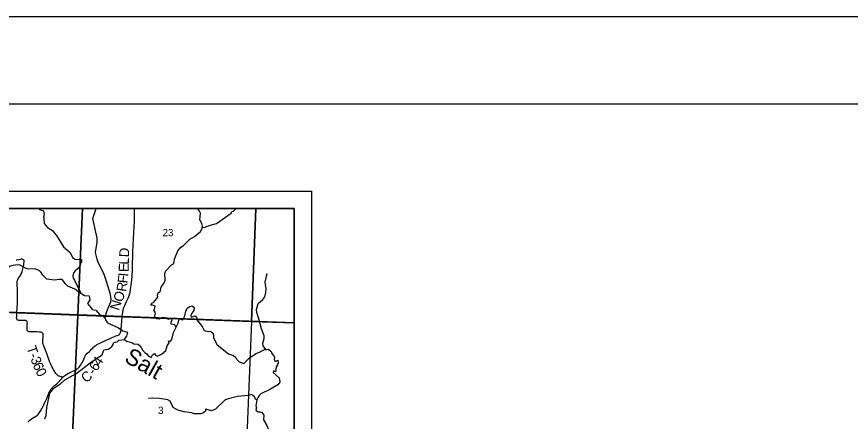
# Model space of a CAD drawing. Extents: x 0 to 34, y 0 to 22.
# Drawn here: x 7.308 to 12.092, y 19.68 to 22 of the extents above; entities that cross this region are included whole.
import ezdxf

# ---------------------------------------------------------------- set-up
doc = ezdxf.new("R2010")
doc.units = 0
for name, color, linetype in [('GM_X_County_Road', 7, 'Continuous'), ('GM_X_County_Road_Text', 7, 'Continuous'), ('GM_X_Minor_River', 7, 'Continuous'), ('GM_X_Minor_River_Text', 7, 'Continuous'), ('GM_X_Rail_Line', 7, 'Continuous'), ('GM_X_Section', 7, 'Continuous'), ('GM_X_Section_Text', 7, 'Continuous'), ('GM_X_Township_Road', 7, 'Continuous'), ('GM_X_Township_Road_Text', 7, 'Continuous'), ('GM_X_Unincorporated_Text', 7, 'Continuous'), ('SH_Border', 7, 'Continuous'), ('SH_Cut_Line', 7, 'Continuous'), ('SH_Data', 7, 'Continuous')]:
    doc.layers.add(name, color=color, linetype=linetype)

msp = doc.modelspace()

# ---------------------------------------------------------------- linework, layer by layer
at = {"layer": 'GM_X_County_Road'}
for points in [[(7.9141, 20.2771), (7.9142, 20.2781), (7.9144, 20.28), (7.9154, 20.2936), (7.9168, 20.306), (7.9185, 20.3152), (7.9208, 20.3243), (7.9236, 20.3332), (7.9281, 20.3449), (7.9317, 20.3535), (7.938, 20.3675), (7.948, 20.3866), (7.952, 20.3955), (7.9564, 20.4078), (7.9596, 20.4197), (7.9621, 20.4337), (7.9662, 20.4765), (7.9701, 20.5077), (7.9715, 20.5235), (7.9722, 20.5378), (7.9726, 20.5533), (7.9733, 20.5875), (7.9741, 20.6247), (7.9748, 20.6496), (7.9798, 20.7647), (7.9837, 20.8261), (7.9851, 20.8606), (7.9844, 20.9)], [(7.5721, 19.9341), (7.5765, 19.9372), (7.5828, 19.9414), (7.5878, 19.9451), (7.6019, 19.9536), (7.6152, 19.9603), (7.6312, 19.9682), (7.6433, 19.9738), (7.6512, 19.9783), (7.6591, 19.9835), (7.666, 19.9899), (7.6708, 19.9955), (7.6761, 20.0031), (7.681, 20.0109), (7.6854, 20.0187), (7.6894, 20.027), (7.6929, 20.0355), (7.6985, 20.05), (7.7004, 20.0544), (7.703, 20.0584), (7.7049, 20.0609), (7.709, 20.0657), (7.7136, 20.0699), (7.7183, 20.074), (7.7253, 20.0801), (7.7297, 20.0844), (7.7381, 20.0935), (7.7443, 20.1004), (7.751, 20.107), (7.7558, 20.1111), (7.7609, 20.1148), (7.7662, 20.1181), (7.7771, 20.1239), (7.7939, 20.1321), (7.8596, 20.163), (7.8697, 20.1672), (7.8776, 20.1694), (7.885, 20.1713), (7.8907, 20.1735), (7.8943, 20.1758), (7.8975, 20.1787), (7.9004, 20.1819), (7.9027, 20.1856), (7.9046, 20.1901), (7.9059, 20.1953), (7.9076, 20.2071), (7.9123, 20.2534), (7.9141, 20.2771)], [(7.3715, 19.6746), (7.3776, 19.6805), (7.3843, 19.6867), (7.3917, 19.6923), (7.3997, 19.6979), (7.4224, 19.7122), (7.428, 19.7162), (7.4323, 19.7196), (7.4361, 19.7241), (7.4399, 19.7298), (7.4429, 19.7356), (7.4521, 19.7521), (7.4633, 19.7738), (7.4686, 19.7848), (7.4817, 19.8114), (7.4877, 19.8267), (7.4932, 19.841), (7.4976, 19.8501), (7.5016, 19.8573), (7.5069, 19.8654), (7.5107, 19.8702), (7.5148, 19.8755), (7.5188, 19.8795), (7.5248, 19.8845), (7.5305, 19.8893), (7.5382, 19.8951), (7.5448, 19.9008), (7.5501, 19.9061), (7.5549, 19.9115), (7.5614, 19.9193), (7.5666, 19.9263), (7.5698, 19.931), (7.5721, 19.9341)]]:
    msp.add_lwpolyline(points, dxfattribs=at)
at = {"layer": 'GM_X_Minor_River'}
for points in [[(7.4372, 20.9), (7.4388, 20.8942), (7.4619, 20.8875), (7.4651, 20.8667), (7.4614, 20.853), (7.4648, 20.8428), (7.4654, 20.8137), (7.4859, 20.7911), (7.5133, 20.7742), (7.5228, 20.7603), (7.5361, 20.7452), (7.5774, 20.6803), (7.6147, 20.6473), (7.6277, 20.6193), (7.6414, 20.6107), (7.6512, 20.6085)], [(7.8111, 20.2745), (7.8163, 20.2791), (7.8275, 20.3149), (7.8488, 20.3643), (7.8499, 20.3791), (7.8456, 20.4075), (7.8228, 20.4821), (7.8077, 20.5283), (7.7775, 20.5865), (7.7694, 20.6096), (7.7612, 20.6483), (7.7707, 20.7075), (7.7691, 20.7299), (7.7446, 20.8435), (7.7645, 20.9)], [(8.2227, 20.2186), (8.2148, 20.2333), (8.1944, 20.2366), (8.1947, 20.2479), (8.2003, 20.2616), (8.1908, 20.2695), (8.1791, 20.2642), (8.1582, 20.2739), (8.1456, 20.2757), (8.1252, 20.2665), (8.112, 20.2672), (8.1025, 20.2732), (8.0997, 20.2846), (8.1057, 20.296), (8.1038, 20.3058), (8.0961, 20.3175), (8.1018, 20.3282), (8.1028, 20.34), (8.088, 20.3459), (8.0774, 20.3463), (8.0834, 20.3573), (8.0936, 20.3619), (8.1132, 20.3836), (8.1181, 20.3931), (8.1154, 20.4034), (8.1199, 20.4159), (8.1308, 20.422), (8.1367, 20.4486), (8.1548, 20.4741), (8.1607, 20.489), (8.1579, 20.5276), (8.165, 20.5425), (8.197, 20.5776), (8.2087, 20.5837), (8.2121, 20.5951), (8.2146, 20.6107), (8.2337, 20.6574), (8.2506, 20.6795), (8.2646, 20.6879), (8.3027, 20.7253), (8.3291, 20.7403), (8.3495, 20.7571), (8.3623, 20.7693), (8.3728, 20.7849), (8.3754, 20.7997), (8.3715, 20.8149), (8.3596, 20.836), (8.3621, 20.8728), (8.3567, 20.8849), (8.3456, 20.9)], [(8.3738, 20.7904), (8.3906, 20.7926), (8.4136, 20.8026), (8.4556, 20.8142), (8.5383, 20.8731), (8.5432, 20.883), (8.553, 20.8857), (8.5671, 20.9)], [(7.6538, 20.4297), (7.6424, 20.4387), (7.6026, 20.4559), (7.5878, 20.4679), (7.5687, 20.4928), (7.5543, 20.4938), (7.526, 20.4894), (7.4806, 20.4959), (7.4585, 20.5178), (7.4486, 20.5328), (7.4364, 20.5445), (7.4125, 20.5534), (7.3777, 20.5528), (7.3622, 20.5554), (7.3246, 20.5782), (7.3, 20.5754), (7.2879, 20.5734), (7.2649, 20.5668), (7.2371, 20.5325), (7.2282, 20.5173), (7.2095, 20.4672), (7.2124, 20.4392), (7.2181, 20.4286)], [(7.6512, 20.6085), (7.6804, 20.6091), (7.6793, 20.5966), (7.6655, 20.5597), (7.6429, 20.5421)], [(7.6429, 20.5421), (7.635, 20.5315), (7.6299, 20.5133), (7.6318, 20.5008), (7.6395, 20.4902)], [(8.7314, 20.0914), (8.7386, 20.0914), (8.7229, 20.1133), (8.7213, 20.1284), (8.7283, 20.1554), (8.7279, 20.171), (8.7121, 20.2107), (8.702, 20.2546), (8.687, 20.3042), (8.6846, 20.3213), (8.6943, 20.3547), (8.7203, 20.3788), (8.7319, 20.3936), (8.7382, 20.4183), (8.7389, 20.4418), (8.7377, 20.4517), (8.7349, 20.4786), (8.7463, 20.5276)], [(7.6395, 20.4902), (7.6765, 20.4153)], [(7.6538, 20.4297), (7.6765, 20.4153)], [(7.6765, 20.4153), (7.6971, 20.4006), (7.7236, 20.3996), (7.7283, 20.3765), (7.714, 20.3548), (7.7346, 20.3333), (7.7411, 20.3216), (7.7619, 20.3179), (7.7837, 20.2926), (7.7936, 20.2885), (7.8042, 20.2829), (7.8156, 20.2689), (7.8195, 20.2579), (7.8287, 20.2455), (7.8921, 20.2162), (7.9164, 20.1997), (7.9445, 20.1911), (7.9393, 20.1691), (7.925, 20.1516), (7.9384, 20.1403), (7.9691, 20.1317), (7.9798, 20.1234), (8.0048, 20.1228), (8.0173, 20.1127), (8.0323, 20.0866), (8.0429, 20.0745), (8.0543, 20.0677), (8.065, 20.0534), (8.0791, 20.0466), (8.0881, 20.0622), (8.0991, 20.0695), (8.1075, 20.0567), (8.117, 20.0529), (8.14, 20.0656), (8.1634, 20.0866), (8.1719, 20.1135), (8.1828, 20.1303), (8.1794, 20.1424), (8.1896, 20.1383), (8.1986, 20.1486), (8.2083, 20.1896), (8.2349, 20.2432), (8.2408, 20.2668), (8.2624, 20.2627), (8.274, 20.2852), (8.2781, 20.3121), (8.2863, 20.3281), (8.3018, 20.3381), (8.315, 20.3419), (8.3268, 20.3321), (8.325, 20.3158), (8.3134, 20.2998), (8.3078, 20.2861), (8.3097, 20.2767), (8.332, 20.2844), (8.3416, 20.2719), (8.3428, 20.2613), (8.3718, 20.2232), (8.3844, 20.2005), (8.4091, 20.1953), (8.4189, 20.1965), (8.4296, 20.1886), (8.4368, 20.1784), (8.4369, 20.1587), (8.458, 20.119), (8.5242, 20.0678), (8.5519, 20.0573), (8.5664, 20.0456), (8.5714, 20.0347), (8.5847, 20.0207), (8.6109, 20.0114), (8.646, 20.0468), (8.6826, 20.0694), (8.706, 20.0775), (8.7298, 20.0913), (8.7408, 20.0921), (8.7537, 20.0941), (8.7693, 20.0806), (8.7716, 20.068), (8.7831, 20.0556), (8.7877, 20.0454), (8.7866, 20.034), (8.7912, 20.0238), (8.806, 20.0307), (8.8079, 20.0155), (8.8054, 20.0034), (8.7975, 19.9931), (8.7942, 19.9639), (8.7824, 19.9703), (8.7795, 19.9592), (8.8141, 19.9287), (8.8173, 19.9037), (8.8067, 19.89), (8.7614, 19.8624), (8.7097, 19.8382), (8.6995, 19.8283), (8.6942, 19.8177), (8.6871, 19.8032), (8.6812, 19.7686), (8.684, 19.7577), (8.6806, 19.744)], [(7.6469, 19.9528), (7.7367, 20.0204), (7.7986, 20.0606), (7.8091, 20.0891), (7.8356, 20.093), (7.8533, 20.1083), (7.8612, 20.1197), (7.8642, 20.13), (7.874, 20.1331), (7.885, 20.1358), (7.8948, 20.1446), (7.9268, 20.1501)], [(7.6469, 19.9528), (7.5821, 19.9159), (7.555, 19.8919), (7.5154, 19.8647), (7.4974, 19.8415), (7.4937, 19.8312), (7.4786, 19.7592), (7.4759, 19.7122), (7.4681, 19.6932)], [(8.6868, 19.8014), (8.6791, 19.8066), (8.6722, 19.8202), (8.6608, 19.8304), (8.6513, 19.8337), (8.6388, 19.8287), (8.5756, 19.8215), (8.5162, 19.8068), (8.5018, 19.8014), (8.4491, 19.7491), (8.4256, 19.7403), (8.3945, 19.7492), (8.3893, 19.7359), (8.3768, 19.7259), (8.3655, 19.7225), (8.3272, 19.7234), (8.3128, 19.7282), (8.2972, 19.7315), (8.2699, 19.7337), (8.2327, 19.7448), (8.2065, 19.7602), (8.1885, 19.7954), (8.1756, 19.8029), (8.127, 19.8106), (8.0876, 19.8134), (8.0641, 19.8114)], [(8.6806, 19.744), (8.6936, 19.7338), (8.7038, 19.7343), (8.7156, 19.7298), (8.7255, 19.715), (8.7241, 19.6877), (8.7433, 19.656), (8.7475, 19.6461), (8.7532, 19.6329), (8.7548, 19.6174), (8.7666, 19.6083), (8.7787, 19.6126), (8.7903, 19.5762), (8.826, 19.57), (8.8373, 19.5716), (8.8403, 19.5826), (8.8474, 19.5929), (8.8577, 19.5895), (8.8805, 19.5665), (8.8927, 19.5688), (8.9, 19.5734)]]:
    msp.add_lwpolyline(points, dxfattribs=at)
at = {"layer": 'GM_X_Rail_Line'}
for points in [[(6.6357, 20.3306), (7.3096, 20.3035), (7.9141, 20.2806), (8.9, 20.2439), (8.9, 20.9), (5.68, 20.9)], [(6.4764, 15.22), (8.4272, 15.1429), (8.9, 15.1329), (8.9, 20.2439), (7.9141, 20.2806), (7.3096, 20.3035), (6.6357, 20.3306)]]:
    msp.add_lwpolyline(points, dxfattribs=at)
at = {"layer": 'GM_X_Section'}
for points in [[(6.6348, 20.3279), (7.6587, 20.2884), (7.6132, 19.2594), (6.5918, 19.2905)], [(7.6587, 20.2884), (8.6557, 20.2521), (8.6142, 19.2215), (7.6132, 19.2594)]]:
    msp.add_lwpolyline(points, close=True, dxfattribs=at)
at = {"layer": 'GM_X_Township_Road'}
for points in [[(7.3097, 20.301), (7.3098, 20.3029), (7.31, 20.305), (7.311, 20.3299), (7.3123, 20.3514), (7.3128, 20.3651), (7.3134, 20.3735), (7.3136, 20.3828), (7.3138, 20.4013), (7.3135, 20.4136), (7.3121, 20.4382), (7.3103, 20.4658), (7.3101, 20.475), (7.3106, 20.4811), (7.3112, 20.4841), (7.312, 20.4871), (7.3131, 20.49), (7.3144, 20.4927), (7.3175, 20.4981), (7.3227, 20.5057), (7.3298, 20.5157), (7.3329, 20.5211), (7.3354, 20.5267), (7.3373, 20.5325), (7.3388, 20.5386), (7.3427, 20.5535), (7.3487, 20.5777), (7.35, 20.5841), (7.3514, 20.5925), (7.3518, 20.596), (7.3514, 20.599), (7.3507, 20.6018), (7.3489, 20.6043), (7.3467, 20.6063), (7.344, 20.6078), (7.3411, 20.6086), (7.338, 20.6089), (7.3348, 20.6088), (7.3309, 20.6082), (7.3111, 20.6049), (7.3055, 20.6039)], [(7.5721, 19.9341), (7.563, 19.9359), (7.5575, 19.9371), (7.5537, 19.9383), (7.5504, 19.9395), (7.5466, 19.9414), (7.5444, 19.9428), (7.5422, 19.9446), (7.5399, 19.9467), (7.5372, 19.9496), (7.5337, 19.9536), (7.5293, 19.9599), (7.5245, 19.9678), (7.5197, 19.9766), (7.515, 19.985), (7.5105, 19.9942), (7.5066, 20.0021), (7.5018, 20.0125), (7.497, 20.0235), (7.4923, 20.0354), (7.4885, 20.0462), (7.4825, 20.0624), (7.4765, 20.0786), (7.4696, 20.0971), (7.4657, 20.1069), (7.4633, 20.1131), (7.4605, 20.1214), (7.459, 20.126), (7.4578, 20.1306), (7.4574, 20.1355), (7.4578, 20.1401), (7.4581, 20.148), (7.4597, 20.1643), (7.4603, 20.1712), (7.4603, 20.1745), (7.4603, 20.1777), (7.4597, 20.1812), (7.4583, 20.1839), (7.4564, 20.1862), (7.4543, 20.1881), (7.4519, 20.1898), (7.4493, 20.1906), (7.4457, 20.1913), (7.4427, 20.1917), (7.4365, 20.1921), (7.4241, 20.1926), (7.4117, 20.1927), (7.3962, 20.1929), (7.3847, 20.1927), (7.3806, 20.1929), (7.3771, 20.1936), (7.3744, 20.1946), (7.3718, 20.1967), (7.3699, 20.1991), (7.3685, 20.2016), (7.368, 20.2044), (7.3679, 20.2081), (7.3679, 20.2112), (7.3684, 20.2205), (7.3692, 20.2396), (7.3694, 20.2455), (7.3691, 20.2498), (7.3682, 20.252), (7.3663, 20.2546), (7.3639, 20.2563), (7.3608, 20.2575), (7.3581, 20.2579), (7.3551, 20.2581), (7.3521, 20.2582), (7.3461, 20.2582), (7.3409, 20.2579), (7.3362, 20.2581), (7.3297, 20.258), (7.3233, 20.2579), (7.3202, 20.2582), (7.3166, 20.2591), (7.3139, 20.2604), (7.3113, 20.2627), (7.3096, 20.2652), (7.3084, 20.2677), (7.3082, 20.2704), (7.3081, 20.2739), (7.3086, 20.2833), (7.3097, 20.301)]]:
    msp.add_lwpolyline(points, dxfattribs=at)
at = {"layer": 'GM_X_Unincorporated_Text'}
for points in [[(7.6858, 20.9), (6.6618, 20.9), (6.6348, 20.3279), (7.6587, 20.2884)], [(8.6799, 20.9), (7.6858, 20.9), (7.6587, 20.2884), (8.6557, 20.2521)], [(8.9, 20.2441), (8.9, 20.9), (8.6799, 20.9), (8.6557, 20.2521)], [(8.9, 19.2054), (8.9, 20.2441), (8.6557, 20.2521), (8.6142, 19.2215)]]:
    msp.add_lwpolyline(points, close=True, dxfattribs=at)
at = {"layer": 'SH_Border'}
msp.add_lwpolyline([(1.5, 21.5), (33.5, 21.5), (33.5, 0.5), (1.5, 0.5)], close=True, dxfattribs=at)
at = {"layer": 'SH_Cut_Line'}
msp.add_lwpolyline([(0, 0), (34, 0), (34, 22), (0, 22)], close=True, dxfattribs=at)
at = {"layer": 'SH_Data'}
for p, q in [((2, 21), (9, 21)), ((9, 21), (9, 14)), ((2.1, 20.9), (8.9, 20.9)), ((8.9, 20.9), (8.9, 14.1))]:
    msp.add_line(p, q, dxfattribs=at)

# ---------------------------------------------------------------- texts
at = {"layer": 'GM_X_County_Road_Text'}
for s, rotation, p in [('D', 88.2075, (7.9527, 20.62)), ('E', 88.0823, (7.95, 20.5349)), ('L', 88.2066, (7.9514, 20.5775)), ('I', 84.3214, (7.9474, 20.5076)), ('R', 81.5174, (7.9359, 20.4204)), ('F', 83.6809, (7.9431, 20.4689)), ('O', 64.6389, (7.9092, 20.3578)), ('N', 72.5834, (7.895, 20.312)), ('4', 56.4052, (7.7858, 19.9921)), ('6', 57.4011, (7.7671, 19.9629)), ('C', 40.2698, (7.7066, 19.8971)), ('-', 59.6615, (7.7557, 19.9432))]:
    msp.add_text(s, height=0.0568, rotation=rotation, dxfattribs=at).set_placement(p)
at = {"layer": 'GM_X_Minor_River_Text'}
msp.add_text('Salt', height=0.09469, rotation=330.4952, dxfattribs=at).set_placement((7.9198, 20.0246))
at = {"layer": 'GM_X_Section_Text'}
for s, height, p in [('23', 0.04186, (8.1454, 20.7412)), ('3', 0.0419, (8.1196, 19.7221))]:
    msp.add_text(s, height=height, rotation=0, dxfattribs=at).set_placement(p)
at = {"layer": 'GM_X_Township_Road_Text'}
for s, rotation, p in [('T', 288.5312, (7.3637, 20.1026)), ('3', 291.0163, (7.3865, 20.038)), ('-', 290.9403, (7.3781, 20.0598)), ('6', 292.0377, (7.3995, 20.0043)), ('0', 296.5689, (7.4146, 19.9674))]:
    msp.add_text(s, height=0.0568, rotation=rotation, dxfattribs=at).set_placement(p)

doc.saveas('drawing.dxf')
